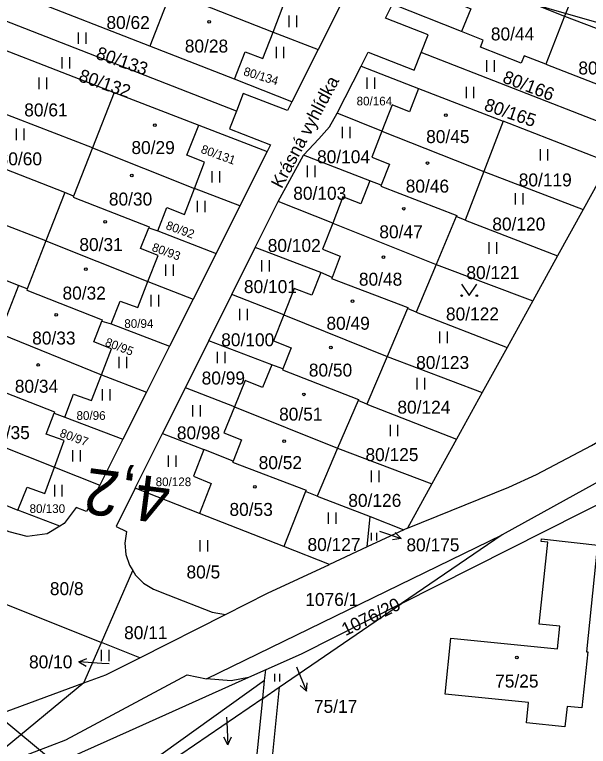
# Model space of a CAD drawing. Extents: x -738085 to -734306, y -1122197 to -1119753.
# Drawn here: x -737296.2 to -737221, y -1121394.5 to -1121298.5 of the extents above; entities that cross this region are included whole.
import ezdxf

# ---------------------------------------------------------------- set-up
doc = ezdxf.new("R2010")
doc.units = 0
for name, color, linetype in [('Hranice parcel', 7, 'Continuous'), ('Parcelní čísla', 7, 'Continuous'), ('Pop  PČ popisy', 7, 'Continuous'), ('Vrstva 1', 7, 'Continuous'), ('Vrstva 7', 7, 'Continuous'), ('Značky budov', 7, 'Continuous'), ('Značky kultur', 7, 'Continuous')]:
    doc.layers.add(name, color=color, linetype=linetype)

msp = doc.modelspace()

# ---------------------------------------------------------------- linework, layer by layer
at = {"layer": 'Hranice parcel'}
for p, q in [((-737221.59, -1121292.43), (-737224.07, -1121298.73)), ((-737237.35, -1121293.38), (-737224.07, -1121298.73)), ((-737278.47, -1121302.66), (-737295.51, -1121295.99)), ((-737275.71, -1121295.53), (-737278.47, -1121302.66)), ((-737275.71, -1121295.53), (-737262.32, -1121300.82)), ((-737253.36, -1121297.08), (-737256.39, -1121303.1)), ((-737237.58, -1121300.73), (-737246.63, -1121297.13)), ((-737267.13, -1121311.18), (-737299.07, -1121298.71)), ((-737224.07, -1121298.73), (-737226.55, -1121305.03)), ((-737224.07, -1121298.73), (-737210.51, -1121303.88)), ((-737262.32, -1121300.82), (-737256.39, -1121303.1)), ((-737298.8, -1121302.68), (-737283.17, -1121308.72)), ((-737267.38, -1121307), (-737278.47, -1121302.66)), ((-737256.39, -1121303.1), (-737259.84, -1121309.95)), ((-737216.07, -1121313.97), (-737242.88, -1121303.5)), ((-737253.91, -1121311.47), (-737250.77, -1121305.27)), ((-737250.77, -1121305.27), (-737243.22, -1121308.2)), ((-737226.55, -1121305.03), (-737213.85, -1121309.92)), ((-737259.84, -1121309.95), (-737267.38, -1121307)), ((-737243.22, -1121308.2), (-737232.12, -1121312.51)), ((-737283.17, -1121308.72), (-737286.01, -1121315.99)), ((-737283.17, -1121308.72), (-737272.07, -1121313.01)), ((-737286.01, -1121315.99), (-737302.35, -1121309.7)), ((-737248.04, -1121313.79), (-737253.91, -1121311.47)), ((-737272.07, -1121313.01), (-737263.09, -1121316.48)), ((-737232.12, -1121312.51), (-737234.66, -1121319.12)), ((-737218.24, -1121317.9), (-737232.12, -1121312.51)), ((-737248.04, -1121313.79), (-737234.66, -1121319.12)), ((-737289.64, -1121321.87), (-737305.38, -1121315.68)), ((-737286.01, -1121315.99), (-737288.49, -1121322.32)), ((-737286.01, -1121315.99), (-737272.61, -1121321.32)), ((-737263.09, -1121316.48), (-737266.67, -1121323.63)), ((-737261.64, -1121323.04), (-737258.32, -1121316.96)), ((-737249.64, -1121320.32), (-737258.32, -1121316.96)), ((-737218.24, -1121317.9), (-737221.63, -1121324.07)), ((-737234.66, -1121319.12), (-737237.11, -1121325.47)), ((-737234.66, -1121319.12), (-737221.63, -1121324.07)), ((-737248.12, -1121320.9), (-737249.64, -1121320.32)), ((-737292.11, -1121328.2), (-737308.52, -1121321.87)), ((-737289.64, -1121321.87), (-737292.11, -1121328.2)), ((-737288.49, -1121322.32), (-737289.64, -1121321.87)), ((-737266.67, -1121323.63), (-737272.61, -1121321.32)), ((-737266.67, -1121323.63), (-737269.79, -1121329.85)), ((-737264.66, -1121329.08), (-737261.64, -1121323.04)), ((-737254.48, -1121325.88), (-737261.64, -1121323.04)), ((-737221.63, -1121324.07), (-737225, -1121330.18)), ((-737238.28, -1121325.02), (-737240.91, -1121331.3)), ((-737237.11, -1121325.47), (-737238.28, -1121325.02)), ((-737237.11, -1121325.47), (-737225, -1121330.18)), ((-737278.63, -1121326.49), (-737277.43, -1121326.89)), ((-737254.48, -1121325.88), (-737240.91, -1121331.3)), ((-737277.43, -1121326.89), (-737269.79, -1121329.85)), ((-737295.72, -1121334.05), (-737311.56, -1121327.86)), ((-737292.11, -1121328.2), (-737294.57, -1121334.52)), ((-737292.11, -1121328.2), (-737278.72, -1121333.54)), ((-737267.73, -1121335.26), (-737264.66, -1121329.08)), ((-737256.04, -1121332.35), (-737264.66, -1121329.08)), ((-737269.79, -1121329.85), (-737272.79, -1121335.84)), ((-737225, -1121330.18), (-737228.25, -1121336.08)), ((-737240.91, -1121331.3), (-737243.54, -1121337.58)), ((-737240.91, -1121331.3), (-737228.25, -1121336.08)), ((-737254.58, -1121333), (-737256.04, -1121332.35)), ((-737295.72, -1121334.05), (-737298.2, -1121340.38)), ((-737294.57, -1121334.52), (-737295.72, -1121334.05)), ((-737278.72, -1121333.54), (-737272.79, -1121335.84)), ((-737270.74, -1121341.31), (-737267.73, -1121335.26)), ((-737260.91, -1121337.9), (-737267.73, -1121335.26)), ((-737272.79, -1121335.84), (-737275.9, -1121342.01)), ((-737228.25, -1121336.08), (-737231.62, -1121342.2)), ((-737244.69, -1121337.1), (-737247.35, -1121343.37)), ((-737243.54, -1121337.58), (-737244.69, -1121337.1)), ((-737260.91, -1121337.9), (-737247.35, -1121343.37)), ((-737243.54, -1121337.58), (-737231.62, -1121342.2)), ((-737284.78, -1121338.73), (-737283.57, -1121339.1)), ((-737283.57, -1121339.1), (-737275.9, -1121342.01)), ((-737298.2, -1121340.38), (-737284.83, -1121345.77)), ((-737275.9, -1121342.01), (-737278.92, -1121348.05)), ((-737273.8, -1121347.49), (-737270.74, -1121341.31)), ((-737262.47, -1121344.47), (-737270.74, -1121341.31)), ((-737231.62, -1121342.2), (-737234.87, -1121348.1)), ((-737247.35, -1121343.37), (-737250.01, -1121349.64)), ((-737247.35, -1121343.37), (-737234.87, -1121348.1)), ((-737261.02, -1121345.02), (-737262.47, -1121344.47)), ((-737284.83, -1121345.77), (-737278.92, -1121348.05)), ((-737276.8, -1121353.49), (-737273.8, -1121347.49)), ((-737267.37, -1121349.97), (-737273.8, -1121347.49)), ((-737278.92, -1121348.05), (-737282.01, -1121354.22)), ((-737234.87, -1121348.1), (-737238.24, -1121354.22)), ((-737251.16, -1121349.15), (-737253.84, -1121355.43)), ((-737250.01, -1121349.64), (-737251.16, -1121349.15)), ((-737250.01, -1121349.64), (-737238.24, -1121354.22)), ((-737267.37, -1121349.97), (-737253.84, -1121355.43)), ((-737291.05, -1121350.8), (-737289.65, -1121351.33)), ((-737289.65, -1121351.33), (-737282.01, -1121354.22)), ((-737304.29, -1121352.6), (-737290.98, -1121357.9)), ((-737280.39, -1121360.68), (-737276.8, -1121353.49)), ((-737276.8, -1121353.49), (-737271.38, -1121355.58)), ((-737282.01, -1121354.22), (-737285.04, -1121360.26)), ((-737238.24, -1121354.22), (-737241.48, -1121360.11)), ((-737253.84, -1121355.43), (-737256.52, -1121361.71)), ((-737253.84, -1121355.43), (-737241.48, -1121360.11)), ((-737267.56, -1121357.1), (-737271.38, -1121355.58)), ((-737290.98, -1121357.9), (-737285.04, -1121360.26)), ((-737241.48, -1121360.11), (-737244.68, -1121365.91)), ((-737271.95, -1121363.99), (-737280.39, -1121360.68)), ((-737258.04, -1121361.08), (-737260.88, -1121368.33)), ((-737256.52, -1121361.71), (-737258.04, -1121361.08)), ((-737244.68, -1121365.91), (-737231.38, -1121360.54)), ((-737256.52, -1121361.71), (-737249.58, -1121364.4)), ((-737290.3, -1121365.66), (-737295.78, -1121363.53)), ((-737260.88, -1121368.33), (-737271.95, -1121363.99)), ((-737249.99, -1121368.38), (-737249.58, -1121364.4)), ((-737249.58, -1121364.4), (-737245.14, -1121366.12)), ((-737244.68, -1121365.91), (-737245.14, -1121366.12)), ((-737271.03, -1121385.68), (-737232.28, -1121366.78)), ((-737245.14, -1121366.12), (-737249.99, -1121368.38)), ((-737232.28, -1121366.78), (-737245.48, -1121375.81)), ((-737319.01, -1121367.21), (-737284.83, -1121380.9)), ((-737254.91, -1121370.67), (-737260.88, -1121368.33)), ((-737249.99, -1121368.38), (-737254.91, -1121370.67)), ((-737281.14, -1121370.78), (-737280.73, -1121371.45)), ((-737284.83, -1121380.9), (-737280.73, -1121371.45)), ((-737280.73, -1121371.45), (-737280.35, -1121372.06)), ((-737261.5, -1121386.77), (-737245.48, -1121375.81)), ((-737279.8, -1121382.92), (-737268.56, -1121377.23)), ((-737270.29, -1121376.94), (-737268.56, -1121377.23)), ((-737287.14, -1121386.22), (-737284.83, -1121380.9)), ((-737279.8, -1121382.92), (-737284.83, -1121380.9)), ((-737263.28, -1121384.52), (-737265.53, -1121385.53)), ((-737263.42, -1121385.89), (-737263.28, -1121384.52)), ((-737287.14, -1121386.22), (-737300.28, -1121397.07)), ((-737267.83, -1121385.94), (-737271.03, -1121385.68)), ((-737265.53, -1121385.53), (-737267.83, -1121385.94)), ((-737263.66, -1121388.25), (-737263.42, -1121385.89)), ((-737261.5, -1121386.77), (-737265.43, -1121425.13)), ((-737263.66, -1121388.25), (-737261.5, -1121386.77)), ((-737263.66, -1121388.25), (-737283.96, -1121402.13)), ((-737267.42, -1121424.92), (-737263.66, -1121388.25)), ((-737301.77, -1121398.36), (-737289.5, -1121393.71))]:
    msp.add_line(p, q, dxfattribs=at)
for points in [[(-737262.32, -1121300.82), (-737261, -1121297.36), (-737263.32, -1121296.46), (-737262.27, -1121293.69)], [(-737237.35, -1121293.38), (-737238.71, -1121296.81), (-737236.39, -1121297.75), (-737237.58, -1121300.73)], [(-737242.88, -1121303.5), (-737241.97, -1121301.17), (-737247.57, -1121298.99), (-737246.63, -1121297.13)], [(-737226.55, -1121305.03), (-737229.38, -1121303.94), (-737229.75, -1121304.88), (-737235.1, -1121302.79), (-737234.74, -1121301.86), (-737237.58, -1121300.73)], [(-737267.38, -1121307), (-737265.99, -1121303.38), (-737263.65, -1121304.27), (-737262.32, -1121300.82)], [(-737250.77, -1121305.27), (-737249.84, -1121303.46), (-737243.79, -1121305.82), (-737242.88, -1121303.5)], [(-737243.22, -1121308.2), (-737244.4, -1121311.26), (-737246.71, -1121310.36), (-737248.04, -1121313.79)], [(-737259.84, -1121309.95), (-737260.42, -1121311.12), (-737266.22, -1121308.86), (-737267.13, -1121311.18)], [(-737267.13, -1121311.18), (-737268.04, -1121313.51), (-737262.66, -1121315.62), (-737263.09, -1121316.48)], [(-737258.32, -1121316.96), (-737256.31, -1121314.82), (-737254.92, -1121313.23), (-737253.91, -1121311.47)], [(-737272.61, -1121321.32), (-737271.29, -1121317.89), (-737273.61, -1121316.96), (-737272.07, -1121313.01)], [(-737248.04, -1121313.79), (-737249.37, -1121317.22), (-737247.05, -1121318.12), (-737248.12, -1121320.9)], [(-737249.64, -1121320.32), (-737250.81, -1121323.34), (-737253.15, -1121322.45), (-737254.48, -1121325.88)], [(-737248.12, -1121320.9), (-737248.17, -1121321.05), (-737238.22, -1121324.88), (-737238.28, -1121325.02)], [(-737277.43, -1121326.89), (-737276.25, -1121323.83), (-737273.94, -1121324.75), (-737272.61, -1121321.32)], [(-737288.49, -1121322.32), (-737288.54, -1121322.46), (-737278.58, -1121326.35), (-737278.63, -1121326.49)], [(-737278.72, -1121333.54), (-737277.39, -1121330.13), (-737279.7, -1121329.23), (-737278.63, -1121326.49)], [(-737254.48, -1121325.88), (-737255.81, -1121329.3), (-737253.5, -1121330.2), (-737254.58, -1121333)], [(-737256.04, -1121332.35), (-737257.21, -1121335.33), (-737259.55, -1121334.46), (-737260.91, -1121337.9)], [(-737254.58, -1121333), (-737254.63, -1121333.14), (-737244.64, -1121336.96), (-737244.69, -1121337.1)], [(-737283.57, -1121339.1), (-737282.37, -1121336.11), (-737280.05, -1121336.95), (-737278.72, -1121333.54)], [(-737294.57, -1121334.52), (-737294.62, -1121334.66), (-737284.73, -1121338.59), (-737284.78, -1121338.73)], [(-737260.91, -1121337.9), (-737262.26, -1121341.34), (-737259.94, -1121342.26), (-737261.02, -1121345.02)], [(-737284.83, -1121345.77), (-737283.51, -1121342.37), (-737285.84, -1121341.47), (-737284.78, -1121338.73)], [(-737262.47, -1121344.47), (-737263.69, -1121347.47), (-737265.98, -1121346.54), (-737267.37, -1121349.97)], [(-737289.65, -1121351.33), (-737288.49, -1121348.31), (-737286.14, -1121349.16), (-737284.83, -1121345.77)], [(-737261.02, -1121345.02), (-737261.08, -1121345.15), (-737251.1, -1121349.01), (-737251.16, -1121349.15)], [(-737300.69, -1121346.71), (-737300.74, -1121346.85), (-737291, -1121350.66), (-737291.05, -1121350.8)], [(-737267.37, -1121349.97), (-737268.76, -1121353.39), (-737266.44, -1121354.33), (-737267.56, -1121357.1)], [(-737290.98, -1121357.9), (-737289.72, -1121354.42), (-737292.06, -1121353.57), (-737291.05, -1121350.8)], [(-737197.31, -1121351.74), (-737212.05, -1121355.65), (-737232.28, -1121366.78)], [(-737231.38, -1121360.54), (-737227.77, -1121358.88), (-737220.56, -1121355.07), (-737216.91, -1121352.96)], [(-737290.3, -1121365.66), (-737291.96, -1121366.65), (-737294.56, -1121367), (-737296.93, -1121366.38), (-737315.66, -1121358.86), (-737317.94, -1121357.6), (-737319.84, -1121355.81), (-737321.2, -1121353.68)], [(-737271.38, -1121355.58), (-737272.73, -1121359.08), (-737270.43, -1121360.04), (-737271.95, -1121363.99)], [(-737267.56, -1121357.1), (-737267.62, -1121357.24), (-737257.98, -1121360.94), (-737258.04, -1121361.08)], [(-737295.78, -1121363.53), (-737294.59, -1121360.53), (-737292.24, -1121361.38), (-737290.98, -1121357.9)], [(-737306.85, -1121359.22), (-737304, -1121360.32), (-737304.36, -1121361.27), (-737298.99, -1121363.36), (-737298.61, -1121362.43), (-737295.78, -1121363.53)], [(-737285.04, -1121360.26), (-737286.78, -1121363.74), (-737288.16, -1121363.19), (-737289.71, -1121365.31), (-737290.3, -1121365.66)], [(-737280.39, -1121360.68), (-737282.89, -1121365.68), (-737281.53, -1121366.37), (-737281.74, -1121367.86), (-737281.61, -1121369.35), (-737281.14, -1121370.78)], [(-737245.48, -1121375.81), (-737217.15, -1121361.48), (-737213.48, -1121360.41)], [(-737227.09, -1121367.33), (-737218.91, -1121368.22), (-737218.95, -1121368.53), (-737219.79, -1121368.45), (-737221.21, -1121382.13), (-737221.01, -1121382.15), (-737221.81, -1121389.5), (-737223.75, -1121389.31), (-737224.02, -1121391.99), (-737229.09, -1121391.48), (-737228.82, -1121388.8), (-737239.72, -1121387.71), (-737238.98, -1121380.35), (-737224.99, -1121381.75), (-737224.7, -1121378.78), (-737227.4, -1121378.53), (-737226.28, -1121367.74), (-737227.13, -1121367.65), (-737227.09, -1121367.33)], [(-737268.56, -1121377.23), (-737263.05, -1121374.45), (-737254.91, -1121370.67)], [(-737280.35, -1121372.06), (-737279.29, -1121373.13), (-737278.02, -1121373.92), (-737276.13, -1121374.66), (-737270.29, -1121376.94)], [(-737245.48, -1121375.81), (-737258.61, -1121382.43), (-737263.28, -1121384.52)], [(-737287.14, -1121386.22), (-737284.26, -1121385.17), (-737279.8, -1121382.92)], [(-737289.5, -1121393.71), (-737273.59, -1121385.14), (-737271.03, -1121385.68)], [(-737335.18, -1121387.07), (-737333.74, -1121390.08), (-737308.72, -1121392.16), (-737298.44, -1121390.37), (-737287.14, -1121386.22)], [(-737265.53, -1121385.53), (-737281.2, -1121392.55), (-737290.36, -1121396.68)], [(-737263.42, -1121385.89), (-737281.35, -1121398.78), (-737283.96, -1121402.13)]]:
    msp.add_lwpolyline(points, dxfattribs=at)
at = {"layer": 'Pop  PČ popisy'}
for p, q in [((-737248.36, -1121366.31), (-737245.523, -1121367.287)), ((-737245.523, -1121367.287), (-737246.306, -1121366.488)), ((-737245.523, -1121367.287), (-737246.632, -1121367.434)), ((-737287.784, -1121383.461), (-737286.75, -1121383.031)), ((-737284.79, -1121383.67), (-737287.784, -1121383.461)), ((-737287.784, -1121383.461), (-737286.82, -1121384.03)), ((-737283.83, -1121383.74), (-737284.79, -1121383.67)), ((-737259.22, -1121384.12), (-737259.06, -1121384.53)), ((-737259.06, -1121384.53), (-737257.936, -1121387.312)), ((-737257.936, -1121387.312), (-737257.847, -1121386.196)), ((-737257.936, -1121387.312), (-737258.775, -1121386.572)), ((-737268.42, -1121390.73), (-737268.39, -1121391.33)), ((-737268.39, -1121391.33), (-737268.233, -1121394.327)), ((-737268.233, -1121394.327), (-737268.785, -1121393.353)), ((-737268.233, -1121394.327), (-737267.785, -1121393.301))]:
    msp.add_line(p, q, dxfattribs=at)
at = {"layer": 'Vrstva 1'}
for points in [[(-737449.698, -1121264.803), (-737986.48, -1121910.906), (-737758.041, -1122100.692), (-737221.26, -1121454.59)], [(-736738.787, -1121437.331), (-737330, -1121267.942), (-737406.294, -1121534.228), (-736815.081, -1121703.617)]]:
    msp.add_lwpolyline(points, close=True, dxfattribs=at)
at = {"layer": 'Značky budov'}
for centre in [(-737270.687, -1121299.459), (-737239.647, -1121311.699), (-737277.817, -1121313.029), (-737242.067, -1121317.989), (-737280.857, -1121319.619), (-737245.177, -1121323.989), (-737284.327, -1121325.699), (-737247.847, -1121330.349), (-737286.867, -1121331.919), (-737251.897, -1121336.129), (-737290.747, -1121337.919), (-737254.717, -1121342.199), (-737293.137, -1121344.499), (-737258.257, -1121348.349), (-737260.857, -1121354.489), (-737264.687, -1121360.489), (-737230.317, -1121382.889)]:
    msp.add_circle(centre, 0.175, dxfattribs=at)
at = {"layer": 'Značky kultur'}
for p, q in [((-737260.191, -1121300.14), (-737260.191, -1121298.64)), ((-737259.19, -1121300.14), (-737259.19, -1121298.64)), ((-737287.831, -1121302.34), (-737287.831, -1121300.84)), ((-737286.83, -1121302.34), (-737286.83, -1121300.84)), ((-737261.881, -1121304.24), (-737261.881, -1121302.74)), ((-737260.88, -1121304.24), (-737260.88, -1121302.74)), ((-737289.981, -1121305.59), (-737289.981, -1121304.09)), ((-737288.98, -1121305.59), (-737288.98, -1121304.09)), ((-737234.271, -1121306.01), (-737234.271, -1121304.51)), ((-737233.27, -1121306.01), (-737233.27, -1121304.51)), ((-737292.991, -1121308.28), (-737292.991, -1121306.78)), ((-737291.99, -1121308.28), (-737291.99, -1121306.78)), ((-737249.951, -1121308.27), (-737249.951, -1121306.77)), ((-737248.95, -1121308.27), (-737248.95, -1121306.77)), ((-737236.961, -1121309.48), (-737236.961, -1121307.98)), ((-737235.96, -1121309.48), (-737235.96, -1121307.98)), ((-737253.221, -1121314.73), (-737253.221, -1121313.23)), ((-737252.22, -1121314.73), (-737252.22, -1121313.23)), ((-737295.971, -1121314.98), (-737295.971, -1121313.48)), ((-737294.97, -1121314.98), (-737294.97, -1121313.48)), ((-737227.251, -1121317.66), (-737227.251, -1121316.16)), ((-737226.25, -1121317.66), (-737226.25, -1121316.16)), ((-737257.781, -1121319.83), (-737257.781, -1121318.33)), ((-737256.78, -1121319.83), (-737256.78, -1121318.33)), ((-737270.311, -1121320.54), (-737270.311, -1121319.04)), ((-737269.31, -1121320.54), (-737269.31, -1121319.04)), ((-737230.511, -1121323.45), (-737230.511, -1121321.95)), ((-737229.51, -1121323.45), (-737229.51, -1121321.95)), ((-737272.241, -1121324.46), (-737272.241, -1121322.96)), ((-737271.24, -1121324.46), (-737271.24, -1121322.96)), ((-737233.981, -1121329.89), (-737233.981, -1121328.39)), ((-737232.98, -1121329.89), (-737232.98, -1121328.39)), ((-737276.381, -1121332.8), (-737276.381, -1121331.3)), ((-737275.38, -1121332.8), (-737275.38, -1121331.3)), ((-737263.791, -1121332.23), (-737263.791, -1121330.73)), ((-737262.79, -1121332.23), (-737262.79, -1121330.73)), ((-737278.311, -1121336.81), (-737278.311, -1121335.31)), ((-737277.31, -1121336.81), (-737277.31, -1121335.31)), ((-737266.681, -1121338.62), (-737266.681, -1121337.12)), ((-737265.68, -1121338.62), (-737265.68, -1121337.12)), ((-737240.421, -1121341.62), (-737240.421, -1121340.12)), ((-737239.42, -1121341.62), (-737239.42, -1121340.12)), ((-737269.601, -1121344.28), (-737269.601, -1121342.78)), ((-737268.6, -1121344.28), (-737268.6, -1121342.78)), ((-737282.491, -1121344.93), (-737282.491, -1121343.43)), ((-737281.49, -1121344.93), (-737281.49, -1121343.43)), ((-737243.391, -1121347.7), (-737243.391, -1121346.2)), ((-737242.39, -1121347.7), (-737242.39, -1121346.2)), ((-737284.671, -1121349.16), (-737284.671, -1121347.66)), ((-737283.67, -1121349.16), (-737283.67, -1121347.66)), ((-737272.841, -1121351.25), (-737272.841, -1121349.75)), ((-737271.84, -1121351.25), (-737271.84, -1121349.75)), ((-737246.931, -1121353.85), (-737246.931, -1121352.35)), ((-737245.93, -1121353.85), (-737245.93, -1121352.35)), ((-737288.561, -1121357.18), (-737288.561, -1121355.68)), ((-737287.56, -1121357.18), (-737287.56, -1121355.68)), ((-737276.041, -1121357.87), (-737276.041, -1121356.37)), ((-737275.04, -1121357.87), (-737275.04, -1121356.37)), ((-737249.401, -1121359.86), (-737249.401, -1121358.36)), ((-737248.4, -1121359.86), (-737248.4, -1121358.36)), ((-737290.961, -1121361.74), (-737290.961, -1121360.24)), ((-737289.96, -1121361.74), (-737289.96, -1121360.24)), ((-737255.041, -1121365.36), (-737255.041, -1121363.86)), ((-737254.04, -1121365.36), (-737254.04, -1121363.86)), ((-737249.392, -1121367.52), (-737249.392, -1121366.515)), ((-737248.722, -1121367.52), (-737248.722, -1121366.515)), ((-737271.861, -1121368.98), (-737271.861, -1121367.48)), ((-737270.86, -1121368.98), (-737270.86, -1121367.48)), ((-737284.821, -1121383.39), (-737284.821, -1121381.89)), ((-737283.82, -1121383.39), (-737283.82, -1121381.89)), ((-737262.092, -1121386.02), (-737262.092, -1121385.015)), ((-737261.422, -1121386.02), (-737261.422, -1121385.015))]:
    msp.add_line(p, q, dxfattribs=at)
msp.add_lwpolyline([(-737237.58, -1121333.889), (-737236.58, -1121335.39), (-737235.58, -1121333.889)], dxfattribs=at)
for centre in [(-737237.58, -1121335.389), (-737235.58, -1121335.389)]:
    msp.add_circle(centre, 0.1, dxfattribs=at)

# ---------------------------------------------------------------- texts
at = {"layer": 'Parcelní čísla'}
for s, height, p in [('80/62', 1.7, (-737284.173, -1121300.4)), ('80/44', 1.7, (-737233.743, -1121301.9)), ('80/28', 1.7, (-737273.893, -1121303.49)), ('80/118', 1.7, (-737222.265, -1121306.37)), ('80/164', 1.14, (-737251.356, -1121310.43)), ('80/61', 1.7, (-737294.953, -1121311.87)), ('80/45', 1.7, (-737242.233, -1121315.37)), ('80/29', 1.7, (-737280.893, -1121316.81)), ('80/60', 1.7, (-737298.313, -1121318.29)), ('80/104', 1.7, (-737256.545, -1121318.02)), ('80/119', 1.7, (-737230.085, -1121321.06)), ('80/46', 1.7, (-737244.913, -1121321.87)), ('80/30', 1.7, (-737283.853, -1121323.57)), ('80/103', 1.7, (-737259.665, -1121322.81)), ('80/120', 1.7, (-737233.555, -1121326.85)), ('80/47', 1.7, (-737248.373, -1121327.87)), ('80/31', 1.7, (-737287.723, -1121329.54)), ('80/102', 1.7, (-737263.015, -1121329.66)), ('80/121', 1.7, (-737236.955, -1121333.22)), ('80/48', 1.7, (-737251.053, -1121334.09)), ('80/101', 1.7, (-737266.135, -1121335.06)), ('80/32', 1.7, (-737289.933, -1121335.91)), ('80/122', 1.7, (-737239.635, -1121338.65)), ('80/49', 1.7, (-737255.313, -1121339.87)), ('80/94', 1.14, (-737281.829, -1121339.63)), ('80/33', 1.7, (-737293.913, -1121341.81)), ('80/100', 1.7, (-737269.115, -1121342.04)), ('80/123', 1.7, (-737243.545, -1121345.02)), ('80/50', 1.7, (-737257.623, -1121346.02)), ('80/99', 1.7, (-737271.683, -1121347.06)), ('80/34', 1.7, (-737296.193, -1121348.14)), ('80/124', 1.7, (-737246.005, -1121350.88)), ('80/96', 1.14, (-737288.099, -1121351.7)), ('80/51', 1.7, (-737261.523, -1121351.8)), ('80/35', 1.7, (-737299.913, -1121354.22)), ('80/98', 1.7, (-737274.933, -1121354.25)), ('80/125', 1.7, (-737250.195, -1121357.11)), ('80/52', 1.7, (-737264.203, -1121358.16)), ('80/128', 1.14, (-737277.716, -1121360.4)), ('80/126', 1.7, (-737252.445, -1121363.12)), ('80/130', 1.14, (-737294.256, -1121363.92)), ('80/53', 1.7, (-737268.033, -1121364.3)), ('80/127', 1.7, (-737257.795, -1121368.91)), ('80/175', 1.7, (-737244.82, -1121368.956)), ('80/5', 1.7, (-737273.671, -1121372.51)), ('80/8', 1.7, (-737291.591, -1121374.7)), ('1076/1', 1.7, (-737258.085, -1121376.12)), ('80/11', 1.7, (-737281.853, -1121380.48)), ('80/10', 1.7, (-737294.326, -1121384.31)), ('75/25', 1.7, (-737233.18, -1121386.83)), ('75/17', 1.7, (-737256.95, -1121390.153))]:
    msp.add_text(s, height=height, dxfattribs=at).set_placement(p)
for s, height, rotation, p in [('80/133', 1.7, 341, (-737285.672, -1121304.267)), ('80/134', 1.14, 343, (-737266.286, -1121306.446)), ('80/132', 1.7, 341, (-737287.942, -1121307.217)), ('80/166', 1.7, 339, (-737232.33, -1121307.378)), ('80/165', 1.7, 341, (-737234.752, -1121311.037)), ('80/131', 1.14, 340, (-737271.878, -1121316.627)), ('80/92', 1.14, 340, (-737276.472, -1121326.629)), ('80/93', 1.14, 340, (-737278.302, -1121329.499)), ('80/95', 1.14, 339, (-737284.45, -1121341.945)), ('80/97', 1.14, 340, (-737290.392, -1121353.879)), ('1076/20', 1.7, 26, (-737252.807, -1121380.096))]:
    msp.add_text(s, height=height, rotation=rotation, dxfattribs=at).set_placement(p)
at = {"layer": 'Pop  PČ popisy'}
msp.add_text('Krásná vyhlídka', height=1.7, rotation=62, dxfattribs=at).set_placement((-737261.184, -1121321.446))
at = {"layer": 'Vrstva 7'}
msp.add_text('4,2', height=6, rotation=172.5266, dxfattribs=at).set_placement((-737275.534, -1121359.443))

doc.saveas('drawing.dxf')
